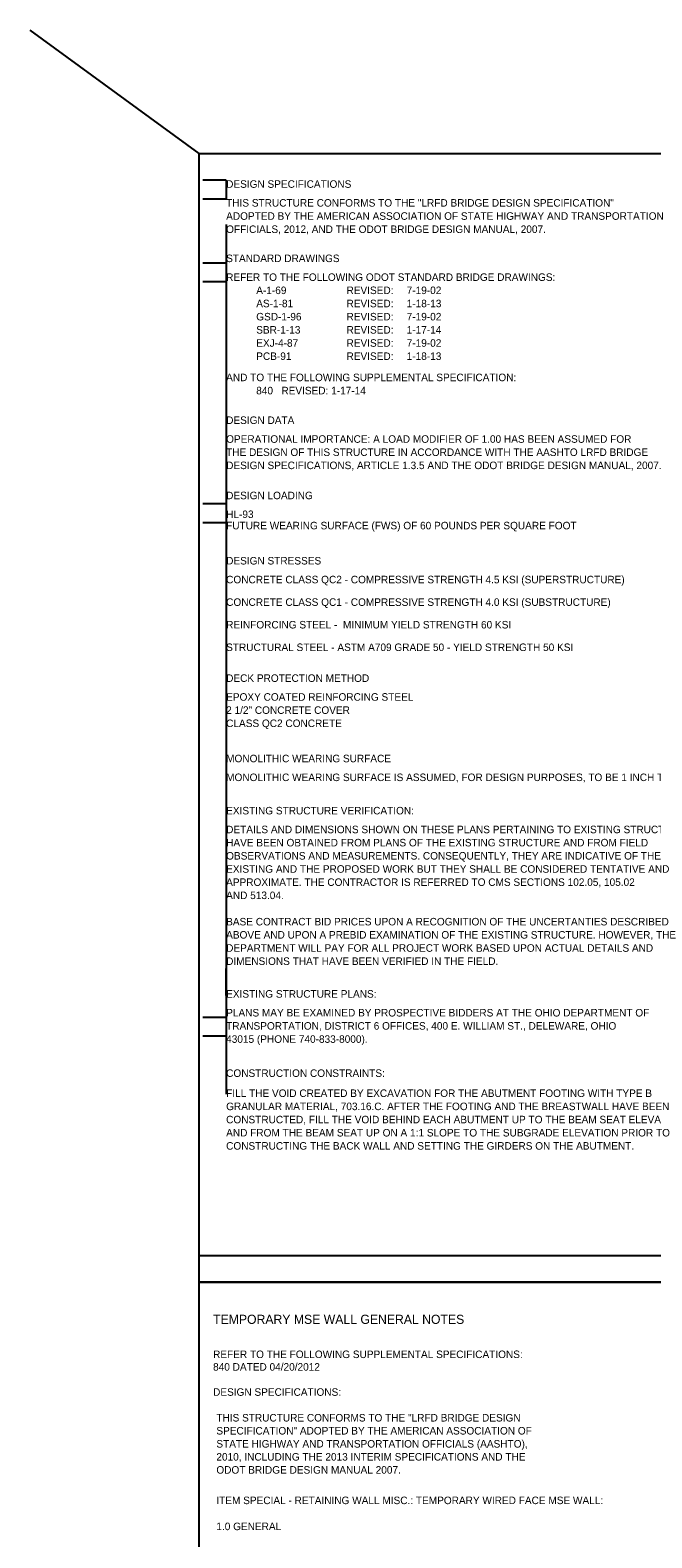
# Model space of a CAD drawing. Extents: x 1530552 to 1530730, y 675304 to 675366.
# Drawn here: x 1530552.04 to 1530563.61, y 675320.6 to 675348.65 of the extents above; entities that cross this region are included whole.
import ezdxf

# ---------------------------------------------------------------- set-up
doc = ezdxf.new("R2010")
doc.units = 0
for name, color, linetype in [('BR_P_Gen_Text', 7, 'Continuous'), ('SC_Scratch1', 7, 'Continuous'), ('SC_Scratch2', 7, 'Continuous'), ('SC_Scratch3', 7, 'Continuous')]:
    doc.layers.add(name, color=color, linetype=linetype)

msp = doc.modelspace()

# ---------------------------------------------------------------- linework, layer by layer
at = {"layer": 'BR_P_Gen_Text'}
msp.add_line((1530555.188, 675346.353), (1530552.04, 675348.646), dxfattribs=at)
for points in [[(1530555.188, 675346.353), (1530585.688, 675346.353), (1530585.688, 675325.353), (1530555.188, 675325.353)], [(1530555.188, 675325.353), (1530585.688, 675325.353), (1530585.688, 675304.353), (1530555.188, 675304.353)]]:
    msp.add_lwpolyline(points, close=True, dxfattribs=at)
at = {"layer": 'SC_Scratch1'}
for p, q in [((1530555.688, 675345.853), (1530555.688, 675345.503)), ((1530555.688, 675345.031), (1530555.688, 675328.854)), ((1530555.688, 675344.873), (1530555.688, 675344.313)), ((1530555.688, 675344.471), (1530555.688, 675344.121))]:
    msp.add_line(p, q, dxfattribs=at)
at = {"layer": 'SC_Scratch2'}
for p, q in [((1530555.688, 675345.853), (1530555.252, 675345.853)), ((1530555.688, 675345.503), (1530555.252, 675345.503)), ((1530555.688, 675344.313), (1530555.252, 675344.313)), ((1530555.688, 675343.963), (1530555.252, 675343.963)), ((1530555.688, 675339.833), (1530555.252, 675339.833)), ((1530555.688, 675339.483), (1530555.252, 675339.483)), ((1530555.688, 675330.281), (1530555.252, 675330.281)), ((1530555.688, 675329.931), (1530555.252, 675329.931))]:
    msp.add_line(p, q, dxfattribs=at)
at = {"layer": 'SC_Scratch3'}
for p, q in [((1530555.688, 675330.69), (1530555.688, 675331.19)), ((1530555.188, 675325.853), (1530585.688, 675325.853))]:
    msp.add_line(p, q, dxfattribs=at)

# ---------------------------------------------------------------- texts
at = {"layer": 'BR_P_Gen_Text'}
for s, height, p in [('DESIGN SPECIFICATIONS', 0.14, (1530555.688, 675345.713)), ('THIS STRUCTURE CONFORMS TO THE "LRFD BRIDGE DESIGN SPECIFICATION" ', 0.14, (1530555.688, 675345.363)), ('ADOPTED BY THE AMERICAN ASSOCIATION OF STATE HIGHWAY AND TRANSPORTATION ', 0.14, (1530555.688, 675345.118)), ('OFFICIALS, 2012, AND THE ODOT BRIDGE DESIGN MANUAL, 2007.', 0.14, (1530555.688, 675344.873)), ('STANDARD DRAWINGS ', 0.14, (1530555.688, 675344.331)), ('REFER TO THE FOLLOWING ODOT STANDARD BRIDGE DRAWINGS:', 0.14, (1530555.688, 675343.981)), ('A-1-69', 0.14, (1530556.248, 675343.736)), ('REVISED:', 0.14, (1530557.928, 675343.736)), ('7-19-02', 0.14, (1530559.048, 675343.736)), ('AS-1-81  ', 0.14, (1530556.248, 675343.491)), ('GSD-1-96', 0.14, (1530556.248, 675343.246)), ('REVISED:', 0.14, (1530557.928, 675343.491)), ('REVISED:', 0.14, (1530557.928, 675343.246)), ('7-19-02', 0.14, (1530559.048, 675343.246)), ('1-18-13', 0.14, (1530559.048, 675343.491)), ('SBR-1-13', 0.14, (1530556.248, 675343.001)), ('REVISED:', 0.14, (1530557.928, 675343.001)), ('1-17-14', 0.14, (1530559.048, 675343.001)), ('EXJ-4-87', 0.14, (1530556.248, 675342.756)), ('REVISED:', 0.14, (1530557.928, 675342.756)), ('7-19-02', 0.14, (1530559.048, 675342.756)), ('PCB-91', 0.14, (1530556.248, 675342.511)), ('REVISED:', 0.14, (1530557.928, 675342.511)), ('1-18-13', 0.14, (1530559.048, 675342.511)), ('AND TO THE FOLLOWING SUPPLEMENTAL SPECIFICATION:', 0.14, (1530555.688, 675342.116)), ('840   REVISED: 1-17-14', 0.14, (1530556.248, 675341.871)), ('DESIGN DATA', 0.14, (1530555.688, 675341.32)), ('THE DESIGN OF THIS STRUCTURE IN ACCORDANCE WITH THE AASHTO LRFD BRIDGE', 0.14, (1530555.688, 675340.725)), ('OPERATIONAL IMPORTANCE: A LOAD MODIFIER OF 1.00 HAS BEEN ASSUMED FOR', 0.14, (1530555.688, 675340.97)), ('DESIGN SPECIFICATIONS, ARTICLE 1.3.5 AND THE ODOT BRIDGE DESIGN MANUAL, 2007.', 0.14, (1530555.688, 675340.48)), ('DESIGN LOADING', 0.14, (1530555.688, 675339.92)), ('HL-93', 0.14, (1530555.688, 675339.57)), ('FUTURE WEARING SURFACE (FWS) OF 60 POUNDS PER SQUARE FOOT', 0.14, (1530555.688, 675339.36)), ('DESIGN STRESSES', 0.14, (1530555.688, 675338.706)), ('CONCRETE CLASS QC2 - COMPRESSIVE STRENGTH 4.5 KSI (SUPERSTRUCTURE)', 0.14, (1530555.688, 675338.356)), ('CONCRETE CLASS QC1 - COMPRESSIVE STRENGTH 4.0 KSI (SUBSTRUCTURE)', 0.14, (1530555.688, 675337.936)), ('REINFORCING STEEL -  MINIMUM YIELD STRENGTH 60 KSI', 0.14, (1530555.688, 675337.516)), ('STRUCTURAL STEEL - ASTM A709 GRADE 50 - YIELD STRENGTH 50 KSI', 0.14, (1530555.688, 675337.096)), ('DECK PROTECTION METHOD', 0.14, (1530555.688, 675336.522)), ('EPOXY COATED REINFORCING STEEL', 0.14, (1530555.688, 675336.172)), ('2 1/2" CONCRETE COVER', 0.14, (1530555.688, 675335.927)), ('CLASS QC2 CONCRETE', 0.14, (1530555.688, 675335.682)), ('MONOLITHIC WEARING SURFACE', 0.14, (1530555.688, 675335.027)), ('MONOLITHIC WEARING SURFACE IS ASSUMED, FOR DESIGN PURPOSES, TO BE 1 INCH THICK.', 0.14, (1530555.688, 675334.677)), ('EXISTING STRUCTURE VERIFICATION:', 0.14, (1530555.688, 675334.057)), ('DETAILS AND DIMENSIONS SHOWN ON THESE PLANS PERTAINING TO EXISTING STRUCTURE ', 0.14, (1530555.688, 675333.707)), ('HAVE BEEN OBTAINED FROM PLANS OF THE EXISTING STRUCTURE AND FROM FIELD ', 0.14, (1530555.688, 675333.462)), ('OBSERVATIONS AND MEASUREMENTS. CONSEQUENTLY, THEY ARE INDICATIVE OF THE', 0.14, (1530555.688, 675333.217)), ('EXISTING AND THE PROPOSED WORK BUT THEY SHALL BE CONSIDERED TENTATIVE AND', 0.14, (1530555.688, 675332.972)), ('APPROXIMATE. THE CONTRACTOR IS REFERRED TO CMS SECTIONS 102.05, 105.02', 0.14, (1530555.688, 675332.727)), ('AND 513.04.', 0.14, (1530555.688, 675332.482)), ('ABOVE AND UPON A PREBID EXAMINATION OF THE EXISTING STRUCTURE. HOWEVER, THE', 0.14, (1530555.688, 675331.747)), ('BASE CONTRACT BID PRICES UPON A RECOGNITION OF THE UNCERTANTIES DESCRIBED', 0.14, (1530555.688, 675331.992)), ('DEPARTMENT WILL PAY FOR ALL PROJECT WORK BASED UPON ACTUAL DETAILS AND', 0.14, (1530555.688, 675331.502)), ('DIMENSIONS THAT HAVE BEEN VERIFIED IN THE FIELD.', 0.14, (1530555.688, 675331.257)), ('EXISTING STRUCTURE PLANS:', 0.14, (1530555.688, 675330.648)), ('PLANS MAY BE EXAMINED BY PROSPECTIVE BIDDERS AT THE OHIO DEPARTMENT OF', 0.14, (1530555.688, 675330.298)), ('TRANSPORTATION, DISTRICT 6 OFFICES, 400 E. WILLIAM ST., DELEWARE, OHIO', 0.14, (1530555.688, 675330.053)), ('43015 (PHONE 740-833-8000).', 0.14, (1530555.688, 675329.808)), ('CONSTRUCTION CONSTRAINTS:', 0.14, (1530555.688, 675329.174)), ('FILL THE VOID CREATED BY EXCAVATION FOR THE ABUTMENT FOOTING WITH TYPE B ', 0.14, (1530555.688, 675328.801)), ('GRANULAR MATERIAL, 703.16.C. AFTER THE FOOTING AND THE BREASTWALL HAVE BEEN ', 0.14, (1530555.688, 675328.556)), ('CONSTRUCTED, FILL THE VOID BEHIND EACH ABUTMENT UP TO THE BEAM SEAT ELEVATION ', 0.14, (1530555.688, 675328.311)), ('AND FROM THE BEAM SEAT UP ON A 1:1 SLOPE TO THE SUBGRADE ELEVATION PRIOR TO ', 0.14, (1530555.688, 675328.066)), ('CONSTRUCTING THE BACK WALL AND SETTING THE GIRDERS ON THE ABUTMENT.', 0.14, (1530555.688, 675327.821)), ('TEMPORARY MSE WALL GENERAL NOTES', 0.17, (1530555.445, 675324.58)), ('REFER TO THE FOLLOWING SUPPLEMENTAL SPECIFICATIONS:', 0.14, (1530555.445, 675323.944)), ('840 DATED 04/20/2012', 0.14, (1530555.445, 675323.71)), ('DESIGN SPECIFICATIONS:', 0.14, (1530555.445, 675323.242)), ('THIS STRUCTURE CONFORMS TO THE "LRFD BRIDGE DESIGN ', 0.14, (1530555.506, 675322.764)), ('SPECIFICATION" ADOPTED BY THE AMERICAN ASSOCIATION OF ', 0.14, (1530555.506, 675322.522)), ('STATE HIGHWAY AND TRANSPORTATION OFFICIALS (AASHTO), ', 0.14, (1530555.506, 675322.279)), ('2010, INCLUDING THE 2013 INTERIM SPECIFICATIONS AND THE ', 0.14, (1530555.506, 675322.037)), ('ODOT BRIDGE DESIGN MANUAL 2007.', 0.14, (1530555.506, 675321.794)), ('ITEM SPECIAL - RETAINING WALL MISC.: TEMPORARY WIRED FACE MSE WALL:', 0.14, (1530555.506, 675321.227)), ('1.0 GENERAL', 0.14, (1530555.506, 675320.743))]:
    msp.add_text(s, height=height, dxfattribs=at).set_placement(p)

doc.saveas('drawing.dxf')
